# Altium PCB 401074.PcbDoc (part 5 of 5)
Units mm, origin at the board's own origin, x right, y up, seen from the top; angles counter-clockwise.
Board outline 70.15 x 35.15 mm, 6 copper layers (Top Layer, Mid-Layer1, Mid-Layer2, Mid-Layer3, Mid-Layer4, Bottom Layer), stack 1.549 mm thick; 239 components, 182 nets, 1034 pads, 1263 vias.
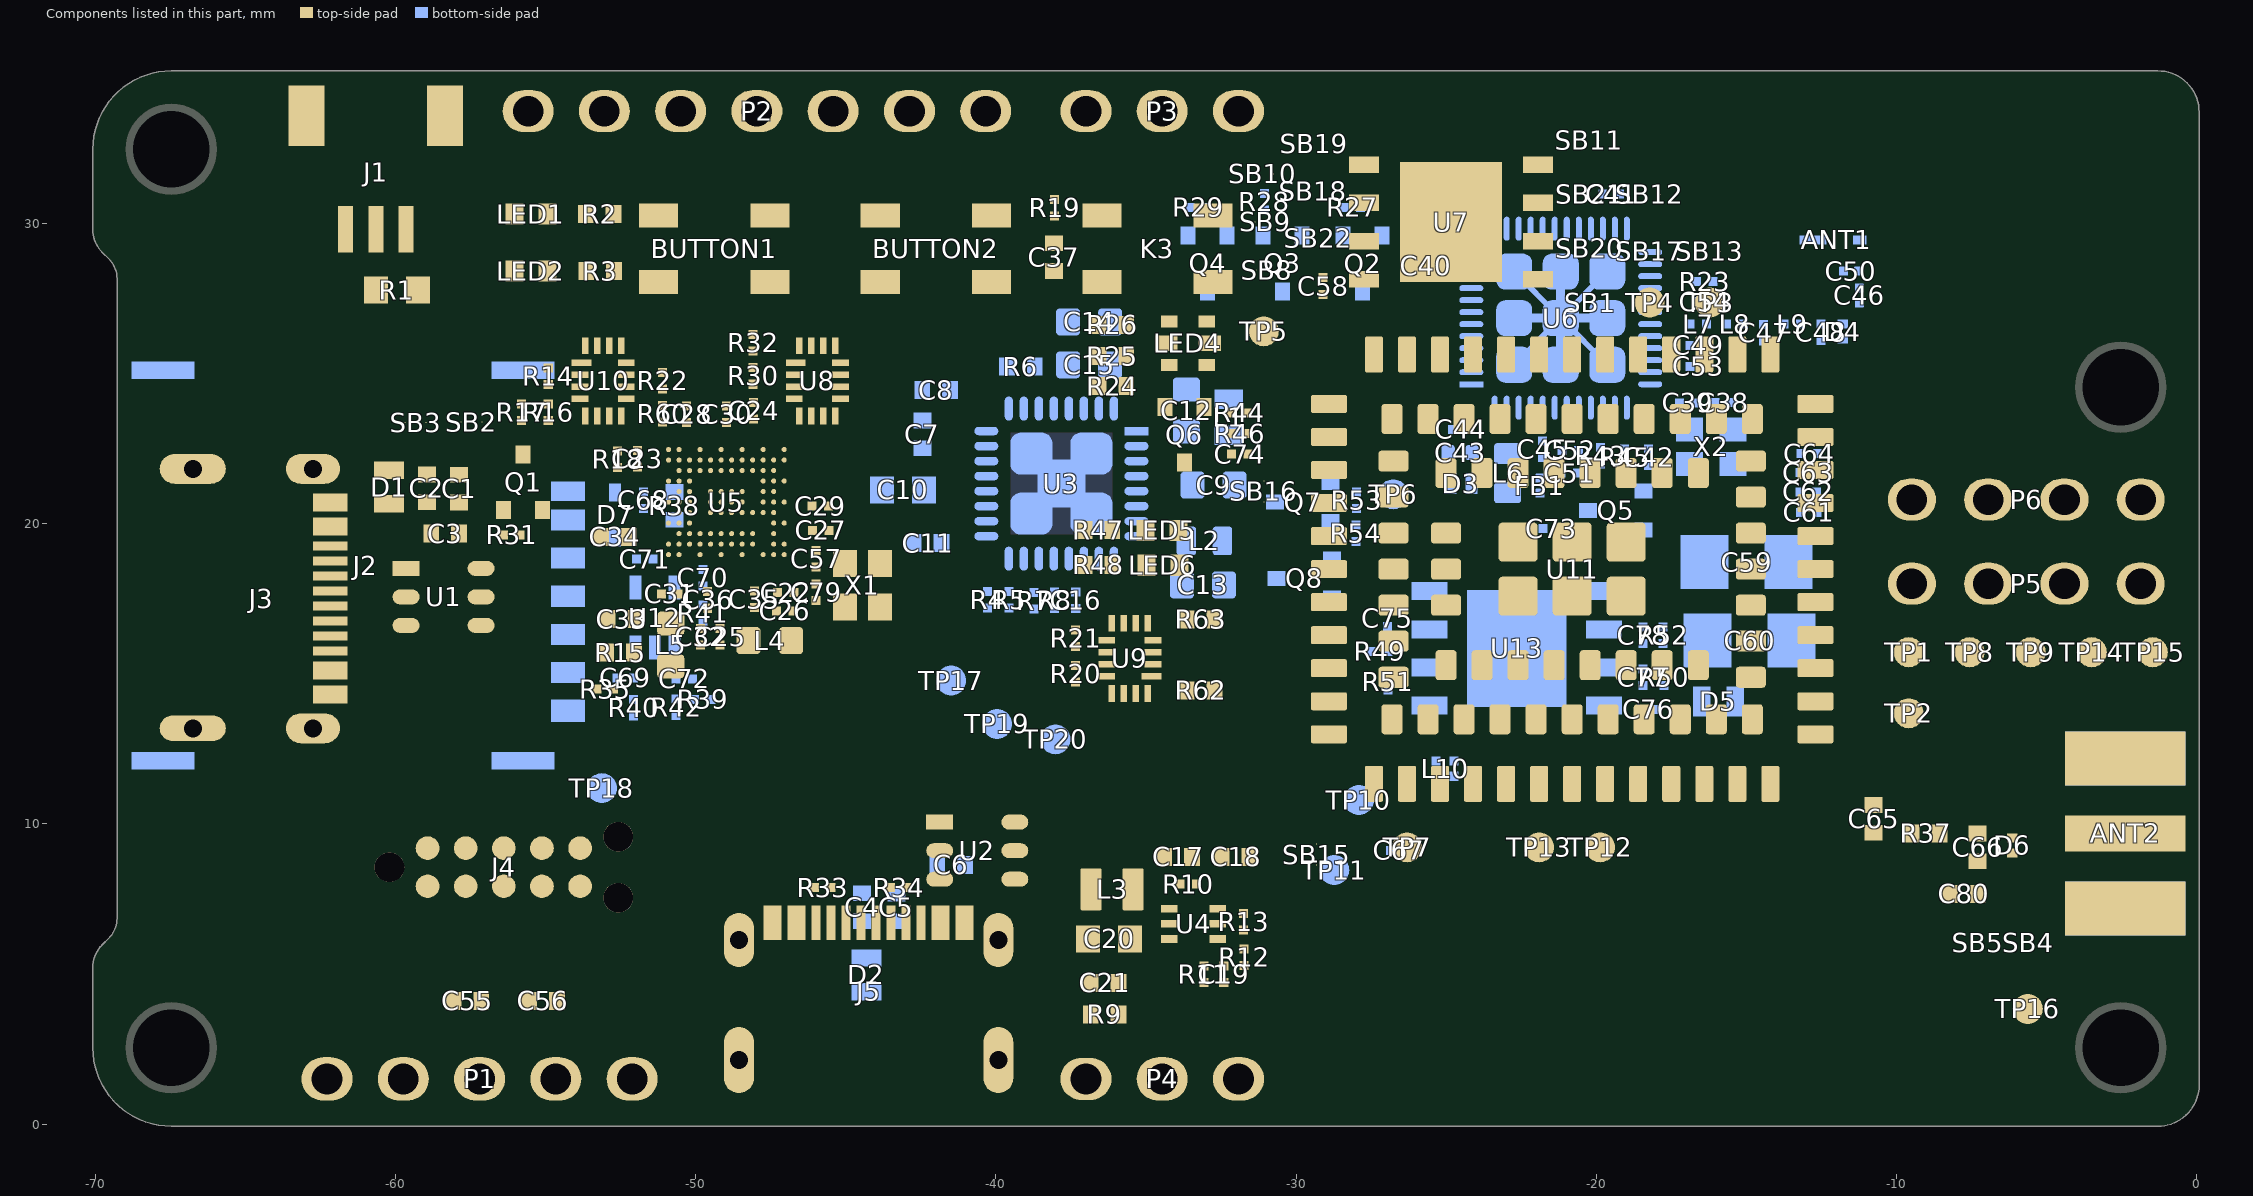
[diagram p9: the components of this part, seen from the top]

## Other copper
Top Layer:
  pour cut-out: -51.551,29.157 -51.175,29.157 -51.175,28.98 -51.766,28.98 -51.766,28.896
  pour cut-out: -54.127,29.797 -54.127,29.794 -54.691,29.794 -54.691,30.853 -54.127,30.853 -54.127,30.3 -53.799,30.3
  pour cut-out: -54.108,28.905 -54.731,28.905 -54.731,28.572 -53.924,28.572
  pour cut-out: -54.108,27.898 -54.919,27.898 -54.919,28.409 -53.807,28.409 -53.807,28.092
  pour cut-out: -56.537,28.962 -56.761,28.962 -56.761,28.92 -56.777,28.905 -56.67,28.799 -56.475,28.799
  pour cut-out: -35.656,18.118 -35.551,18.118 -35.489,18.056 -35.489,18.488 -35.622,18.621
  pour cut-out: -37.512,19.274 -37.513,19.273 -37.513,19.124 -37.364,19.124 -37.34,19.1 -37.241,19.199 -37.047,19.199
  pour cut-out: -35.517,20.32 -35.557,20.28 -35.656,20.28 -35.656,20.104 -35.535,19.983 -35.413,19.983
  pour cut-out: -27.508,14.332 -27.348,14.172 -26.942,14.172 -26.942,13.786 -26.968,13.812 -28.16,13.812 -28.16,13.897 -28.342,14.079
  pour cut-out: -14.271,13.994 -14.271,14.522 -14.328,14.579 -14.52,14.386 -14.625,14.386 -14.625,14.007 -14.562,13.944
  pour cut-out: -4.639,8.33 -4.639,11.379 -0.165,11.379 -0.165,8.073 -0.279,8.073
  pour cut-out: -21.961,12.712 -15.154,12.712 -15.154,14.246 -21.961,14.246
  pour cut-out: -27.661,24.763 -24.64,24.763 -24.64,26.496 -27.661,26.496
  pour cut-out: -26.761,12.713 -20.807,12.713 -20.807,14.246 -26.761,14.246
  pour cut-out: -16.403,30.82 -16.403,30.261 -16.644,30.02 -17.223,29.441 -17.223,29.03 -17.577,28.676 -19.309,28.676 -19.4,28.767 -19.4,30.15 -18.898,30.652 -18.938,30.693
  pour cut-out: -30.022,28.001 -30.022,26.686 -30.165,26.686 -30.165,26.502 -30.674,25.992 -30.934,26.252 -31.123,26.252 -31.123,26.89 -31.383,27.15
  pour cut-out: -30.022,28.001 -28.886,28.001 -28.886,28.466 -29.815,28.466 -29.815,28.313
  pour cut-out: -54.49,25.788 -55.794,25.788 -55.868,25.714 -55.728,25.573 -55.728,24.795 -55.493,24.795 -55.23,24.532 -54.735,25.028 -54.433,25.028
  pour cut-out: -46.682,24.053 -45.378,24.053 -45.304,24.127 -45.444,24.267 -45.444,25.045 -45.678,25.045 -45.941,25.308 -46.437,24.813 -46.739,24.813
  pour cut-out: -22.703,30.734 -22.703,28.298 -20.77,28.298 -20.77,31.045
  pour cut-out: -32.888,27.934 -32.888,26.63 -32.814,26.556 -32.674,26.696 -31.896,26.696 -31.896,26.931 -31.633,27.194 -32.128,27.689 -32.128,27.991
  pour cut-out: -27.979,16.324 -27.962,16.342 -26.562,16.342 -26.562,16.945 -26.948,17.332 -27.889,17.332
  pour cut-out: -32.186,28.569 -31.731,29.024 -31.496,29.024 -31.496,28.637 -31.276,28.416 -31.775,27.917 -32.112,27.917
  pour cut-out: -26.975,32.004 -26.975,28.201 -27.478,28.704 -29.694,28.704 -29.694,29.962 -30.492,30.76 -30.378,30.874 -30.378,32.101 -30.351,32.101 -29.967,32.485
Mid-Layer1:
  pour cut-out: -8.298,7.412 -8.298,5.934 -5.012,5.934 -5.012,7.756
  pour cut-out: 0,12.013 -15.959,12.013 -15.959,7.34 0,7.34
  pour cut-out: -54.511,28.066 -54.179,27.734 -53.848,27.734 -53.848,28.065 -54.097,28.314 -54.176,28.314
Mid-Layer4:
  pour cut-out: -18.517,26.065 -16.907,26.065 -16.907,25.968 ccw(c-16.335,25.968) -15.763,25.968 -15.763,26.065 -13.778,26.065 ccw(c-13.778,26.637) -13.776,26.065 -11.914,26.065 ccw(c-11.914,27.308) -10.672,27.308 -10.672,29.444 ccw(c-11.244,29.444) -11.815,29.444 -11.815,27.308 cw(c-11.914,27.308) -11.914,27.209 -13.778,27.209 ccw(c-13.778,26.637) -13.779,27.209 -18.517,27.209 ccw(c-18.517,26.637)
  pour cut-out: -50.262,19.09 -50.072,19.09 -50.094,19.069 -50.094,18.922 -50.17,18.922 -50.2,18.952
  pour cut-out: -50.709,20.398 -50.459,20.648 -50.459,20.376 -50.516,20.318
Bottom Layer:
  region net GND: -13.448,29.293 -12.134,29.293 -12.134,28.988 -12.201,28.92 -13.717,28.92 -13.829,28.808
  pour cut-out: -27.783,25.872 -27.102,25.849 -27.191,26.137 -27.783,26.111
  pour cut-out: -10.813,27.942 -10.813,27.042 -11.59,27.042 -11.663,27.115 -11.663,27.942
  pour cut-out: -13.147,26.218 -14.047,26.218 -14.047,26.984 -13.974,27.056 -13.147,27.056
  pour cut-out: -15.073,26.218 -15.973,26.218 -15.973,26.984 -15.9,27.056 -15.073,27.056
  pour cut-out: -54.991,15.793 -54.991,14.112 -54.655,13.776 -54.554,13.877 -53.95,13.877 -53.95,15.742 -53.772,15.92
  pour cut-out: -54.825,16.398 -53.644,16.398 -53.562,16.481 -53.712,16.631 -53.712,16.659 -54.57,16.659 -54.781,16.87
  pour cut-out: -39.565,23.581 -35.37,23.581 -35.204,23.415 -35.204,19.692 -36.068,18.828 -39.568,18.828 -40.168,19.427 -40.432,19.427 -40.432,23.289 -39.954,23.766 -39.903,23.766
  pour cut-out: -17.22,25.849 -16.579,25.849 -16.551,25.821 -16.629,25.744 -16.629,25.571 -16.913,25.571 -16.988,25.497 -17.022,25.532 -17.022,25.605
  pour cut-out: -31.264,22.968 -31.735,22.968 -31.764,22.939 -32.292,23.467 -32.92,23.467 -32.92,23.699 -32.853,23.766 -31.261,23.766 -31.248,23.753
  pour cut-out: -34.811,19.825 -34.811,16.622 -35.085,16.622 -35.085,19.61

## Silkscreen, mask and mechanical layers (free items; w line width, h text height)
Top Overlay:
  drawing of 24 lines, arcs and shapes, not listed
  text "BUTTON1" at -51.779,31.209 h1.1
  text "BUTTON2" at -44.41,31.208 h1.1
  text "RESET" at -36.384,31.206 h1.1
  text "-" at -56.473,28.312 h1.5
  text "+" at -64.033,28.239 h1.5
  text "401074" at -10.5,26.899 h1.52
  text "ERR" at -57.607,26.339 h1.1
  text "YYWW" at -9.378,25.729 h1.52
  text "CHG" at -57.607,24.678 h1.1
  text "RGB" at -32.049,24.651 h1.1
  text "S/C" at -9.378,24.332 h1.52
  text "V04" at -6.857,24.326 h1.52
  text "USB1" at -67.488,23.15 h1.52
  text "RI" at -7.38,22.201 h1.27
  text "PKEY" at -5.702,22.182 h1.27
  text "DTR" at -10.324,22.178 h1.27
  text "RST" at -2.59,22.023 h1.27
  text "P6" at -10.778,19.512 h1.1 r90
  text "NET" at -39.878,19.277 h1.1
  text "STA" at -39.868,18.058 h1.1
  text "P5" at -10.698,16.659 h1.1 r90
  text "TX" at -8.282,15.378 h1.14 r90
  text "RX" at -6.187,15.355 h1.14 r90
  text "RTS" at -4.187,15.243 h1.14 r90
  text "CTS" at -2.128,15.178 h1.14 r90
  text "USB2" at -47.16,8.476 h1.52
  text "TP16" at -6.477,2.451 h1.02
  text "nRF93M1-DK" at -26.739,0.344 h2.54
Bottom Overlay:
  circle w0.127: c-26.513,13.971 r0.137
  lines w0.152: -68.55,25.651 -68.55,29.151 -42.55,29.151 -42.55,25.651 -68.55,25.651
  text "P2" at -57.506,32.861 h1.52
  text "P3" at -28.086,31.893 h1.52
  text "1V8" at -37.62,30.205 h1.27 r270
  text "GND" at -32.44,30 h1.27 r270
  text "3V3" at -43.561,29.94 h1.52 r270
  text "P2.01" at -56.134,29.747 h1.27 r270
  text "P2.03" at -51.043,29.688 h1.27 r270
  text "P2.02" at -53.712,29.626 h1.27 r270
  text "P2.04" at -48.286,29.626 h1.27 r270
  text "P2.05" at -45.994,29.532 h1.27 r270
  text "Nordic Semiconductor ASA" at -48.75,27.894 h1.27
  text "LDO_OUT" at -41.78,26.714 h1.27 r270
  text "Otto Nielsens veg 12, 7052 Trondheim, Norway" at -43.55,26.35 h1.27
  text "VDD_nRF54" at -35.326,25.962 h1.27 r270
  text "TP17" at -40.554,15.587 h1.02
  text "eSIM" at -21.845,12.39 h1.27
  text "For evaluation only, not FCC approved for resale" at -5.218,5.183 h1.52
  text "P1.03" at -55.118,3.236 h1.27 r270
  text "P2.00" at -52.717,3.236 h1.27 r270
  text "GND" at -62.758,3.22 h1.27 r270
  text "P1.02" at -57.44,3.22 h1.27 r270
  text "GND" at -32.437,3.226 h1.27 r270
  text "VSYS" at -60.1,3.144 h1.27 r270
  text "VDD_nRF93" at -34.901,3.061 h1.27 r270
  text "3V8" at -37.64,2.77 h1.52 r270
  text "P1" at -63.576,1.118 h1.52
  text "P4" at -28.012,1.041 h1.52
Mechanical 1:
  lines w0.2: -69.766,29.023 cw(c-68.93,29.809) -70.075,29.736 -70.075,32.718 cw(c-67.718,32.718) -67.718,35.075 -1.165,35.075 cw(c-1.164,33.836) 0.075,33.836 0.075,1.165 cw(c-1.164,1.164) -1.164,-0.075 -67.718,-0.075 cw(c-67.718,2.282) -70.075,2.282 -70.053,5.231 cw(c-68.878,5.194) -69.761,5.971 ; -69.764,29.026 cw(c-70.408,28.077) -69.263,28.149 -69.292,6.866 cw(c-70.44,6.902) -69.578,6.143 ; -69.742,5.992 -69.595,6.131 ; -69.761,5.971 -69.76,5.971
Mechanical 3:
  lines w0.127: -70,35 0,35 ; 0,0 0,34
Top Impedance (Mech11):
  lines w0.584: -14.207,11.329 -14.207,10.827 ccw(c-13.056,10.827) -13.056,9.676 -9.586,9.676 ; -8.434,9.676 -7.301,9.676 -2.505,9.676 ; -9.586,9.676 -9.586,9.676
Bottom Impedance (Mech12):
  lines w0.254: -18.207,26.637 -17.502,26.637
  lines w0.356: -17.502,26.637 -16.92,26.637 ; -16.335,25.968 -16.335,26.637 -15.708,26.637 ; -15.073,26.637 -13.778,26.637 ; -13.151,26.637 -11.796,26.637 ccw(c-11.796,27.189) -11.244,27.189 -11.244,27.308 ; -11.244,27.882 -11.244,29.444
Mechanical 15:
  circle w0.1: c-2.54,24.54 r2.5
  circle w0.127: c-2.54,2.54 r2.5
  circle w0.127: c-67.46,2.54 r2.5
  circle w0.127: c-67.46,32.46 r2.5
  lines w0.05: -70,2.54 -70,0 -65.789,0 ; -70,29.789 -70,34 ; -63.501,3.229 -51.809,3.229
  lines w0.126: -49.379,27.375 -49.379,33.279
  lines w0.15: -61.788,6.555 -61.788,12.542 ; -50.987,6.555 -50.987,12.542 ; -29.321,0.764 -29.321,6.751 ; -18.52,0.764 -18.52,6.751 ; -17.321,0.764 -17.321,6.751 ; -6.52,0.764 -6.52,6.751
Mechanical 30:
  circle w0.152: c-8.555,9.57 r0.173
  circle w0.152: c-7.755,9.57 r0.173
  circle w0.152: c-6.955,9.57 r0.173
  circle w0.152: c-6.155,9.57 r0.173
  circle w0.152: c-5.355,9.57 r0.173
  lines w0.05: -69.195,17.5 -2.055,17.5 ; -36.027,9.57 -36.027,32.43 ; -5.633,5 -5.633,33.817
  lines w0.126: -11.426,28.386 -0.655,28.386
  lines w0.15: -4.595,9.57 ccw(c-4.595,12.11) -2.055,12.11

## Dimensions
-1.164,-0.075 to -2.54,24.54 on Mechanical 3
-67.46,32.46 to -67.46,-0.075 on Mechanical 3
-2.54,2.54 to -2.54,24.54 on Mechanical 3
-67.46,32.46 to -67.46,2.54 on Mechanical 3
-67.46,2.54 to -2.54,2.54 on Mechanical 3
-70.075,5.211 to -67.46,2.54 on Mechanical 3
-70,35 to 0,35 on Mechanical 3
-70,35 to -67.46,-0.075 on Mechanical 3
